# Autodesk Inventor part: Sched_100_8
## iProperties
Shininess: 64.0
Length Units: 11272
Angle Units: 11279
Time Units: 11290
Mass Units: 11286
Length Display Precision: 3
Angle Display Precision: 2
Compacted: True
Part Number: Sched_100_8
Document SubType Name: Modeling
Created: 2005-05
Designer: John Blackburn
Manufacturer: Standard
Standards Organization: Custom
Material: Aluminum-6061
Density: 0.0
Volumn: 0.0
Area: 0.0
PropertySet Name: Model Information
Control State: 0
Master: False
Checked Out: False
Author: John Blackburn
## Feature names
1. Extrusion1
